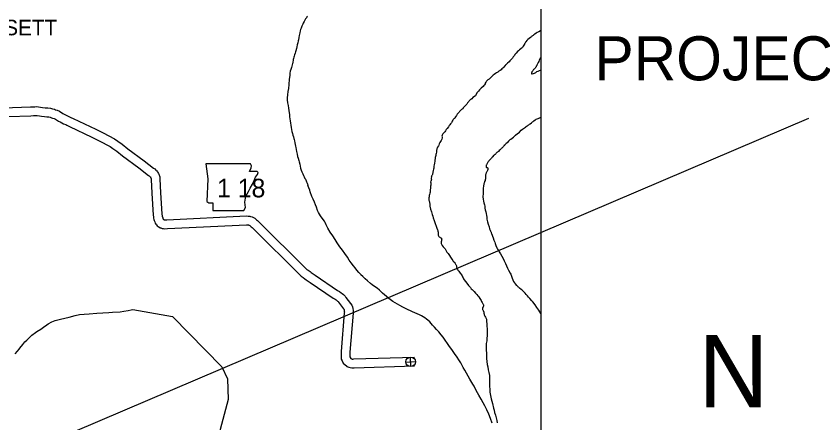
# Model space of a CAD drawing. Extents: x -117616 to 64730, y 54117 to 789866.
# Drawn here: x 62107.1 to 62382.1, y 55866.6 to 56005.1 of the extents above; entities that cross this region are included whole.
import ezdxf

# ---------------------------------------------------------------- set-up
doc = ezdxf.new("R2010")
doc.units = 0
for name, color, linetype in [('10', 7, 'Continuous'), ('21', 7, 'Continuous'), ('26', 7, 'Continuous'), ('3', 7, 'Continuous'), ('6', 7, 'Continuous'), ('9', 7, 'Continuous'), ('Default', 7, 'Continuous'), ('R_Draft', 7, 'Continuous'), ('R_No Plot', 7, 'Continuous')]:
    doc.layers.add(name, color=color, linetype=linetype)

msp = doc.modelspace()

# ---------------------------------------------------------------- linework, layer by layer
at = {"layer": '10'}
for points in [[(62096.7, 55973.7), (62111.98, 55974.22), (62112.83, 55974.27), (62113.46, 55974.3), (62114, 55974.31), (62114.69, 55974.23), (62115.44, 55974.13), (62116.12, 55974.04), (62117.04, 55973.91), (62117.85, 55973.88), (62118.77, 55973.75), (62119.49, 55973.59), (62120.15, 55973.4), (62120.48, 55973.27), (62121.13, 55973.06), (62121.88, 55972.72), (62123.04, 55972.01), (62123.52, 55971.76), (62124.1, 55971.46), (62124.59, 55971.19), (62125.26, 55970.9), (62125.72, 55970.67), (62126.59, 55970.27), (62134.27, 55966.66), (62136.8, 55965.35), (62140.66, 55963.31), (62141.74, 55962.58), (62143.22, 55961.54), (62145.18, 55960), (62150.71, 55955.82), (62153.97, 55953.35), (62154.4, 55953.09), (62154.74, 55952.72), (62154.84, 55952.62), (62155.05, 55952.42), (62155.26, 55952.17), (62155.46, 55951.91), (62155.67, 55951.5), (62155.76, 55951.28), (62155.88, 55951.02), (62155.97, 55950.71), (62156.05, 55950.39), (62156.14, 55949.76), (62156.35, 55945.01)], [(62096.82, 55970.7), (62112.12, 55971.22), (62112.99, 55971.28), (62113.55, 55971.3), (62113.85, 55971.31), (62114.32, 55971.25), (62115.04, 55971.16), (62115.71, 55971.07), (62116.78, 55970.92), (62117.59, 55970.89), (62118.22, 55970.8), (62118.74, 55970.68), (62119.2, 55970.55), (62119.48, 55970.44), (62120.05, 55970.26), (62120.47, 55970.07), (62121.57, 55969.39), (62122.14, 55969.1), (62122.69, 55968.81), (62123.27, 55968.49), (62123.99, 55968.18), (62124.43, 55967.96), (62125.33, 55967.55), (62132.94, 55963.97), (62135.41, 55962.69), (62139.11, 55960.74), (62140.03, 55960.11), (62141.43, 55959.13), (62143.34, 55957.62), (62148.9, 55953.43), (62152.28, 55950.87), (62152.47, 55950.75), (62152.57, 55950.64), (62152.76, 55950.45), (62152.86, 55950.36), (62152.91, 55950.3), (62152.91, 55950.29), (62152.95, 55950.23), (62153.03, 55950.03), (62153.06, 55949.97), (62153.07, 55949.93), (62153.1, 55949.81), (62153.14, 55949.5), (62153.35, 55944.87)], [(62153.35, 55944.84), (62153.83, 55937.41), (62153.89, 55936.77), (62153.94, 55936.36), (62154.05, 55935.87), (62154.19, 55935.56), (62154.27, 55935.36), (62154.31, 55935.26), (62154.36, 55935.07), (62154.52, 55934.67), (62154.78, 55934.3), (62154.92, 55934.09), (62155.23, 55933.77), (62155.49, 55933.53), (62155.74, 55933.34), (62156.18, 55933.1), (62156.4, 55933.02), (62156.7, 55932.9), (62156.84, 55932.87), (62156.96, 55932.84), (62157.18, 55932.78), (62157.61, 55932.71), (62158.68, 55932.8), (62185.61, 55934.08), (62185.99, 55934.05), (62186.22, 55934.04), (62186.39, 55934.02), (62186.45, 55934.01), (62186.56, 55933.99), (62186.58, 55933.97), (62186.74, 55933.84), (62187.2, 55933.41), (62187.53, 55933.2), (62204.28, 55916.55), (62204.98, 55916.1), (62205.49, 55915.73), (62205.95, 55915.38), (62206.67, 55914.88), (62207.35, 55914.41), (62215.13, 55909.12), (62215.82, 55908.76), (62216.16, 55908.53), (62216.36, 55908.37), (62216.71, 55908.09), (62216.88, 55907.93), (62217, 55907.71), (62218.74, 55905.41), (62218.91, 55905.19), (62218.94, 55905.09), (62218.98, 55904.71), (62218.99, 55904.3), (62218.98, 55904.14), (62217.89, 55890.88), (62217.87, 55890.22), (62217.86, 55889.73), (62217.87, 55889.3), (62217.91, 55888.85), (62217.96, 55888.32), (62218.21, 55887.74), (62218.61, 55887), (62219.79, 55885.93), (62219.89, 55885.88), (62220.16, 55885.73), (62220.5, 55885.61), (62220.94, 55885.45), (62221.49, 55885.36), (62222.03, 55885.37), (62222.38, 55885.39), (62242.94, 55886.02)], [(62156.35, 55945.03), (62156.82, 55937.65), (62156.88, 55937.09), (62156.9, 55936.85), (62156.9, 55936.84), (62156.95, 55936.76), (62157.06, 55936.48), (62157.16, 55936.22), (62157.2, 55936.07), (62157.26, 55935.98), (62157.26, 55935.98), (62157.32, 55935.93), (62157.4, 55935.85), (62157.41, 55935.85), (62157.45, 55935.83), (62157.59, 55935.78), (62157.72, 55935.75), (62157.76, 55935.73), (62158.48, 55935.79), (62185.68, 55937.09), (62186.17, 55937.04), (62186.4, 55937.04), (62186.76, 55937), (62187.04, 55936.96), (62187.58, 55936.83), (62188.03, 55936.62), (62188.44, 55936.33), (62188.74, 55936.07), (62189.05, 55935.79), (62189.43, 55935.53), (62206.15, 55918.91), (62206.66, 55918.59), (62207.29, 55918.14), (62207.72, 55917.81), (62208.39, 55917.35), (62209.05, 55916.88), (62216.68, 55911.7), (62217.35, 55911.34), (62217.96, 55910.94), (62218.26, 55910.69), (62218.69, 55910.35), (62219.28, 55909.78), (62219.52, 55909.36), (62221.11, 55907.25), (62221.58, 55906.66), (62221.77, 55906.18), (62221.9, 55905.57), (62221.98, 55904.91), (62221.99, 55904.3), (62221.98, 55903.98), (62220.89, 55890.71), (62220.87, 55890.13), (62220.86, 55889.72), (62220.87, 55889.47), (62220.9, 55889.13), (62220.9, 55889.1), (62221.19, 55888.59), (62221.2, 55888.59), (62221.41, 55888.47), (62221.51, 55888.44), (62221.7, 55888.37), (62221.7, 55888.36), (62221.93, 55888.37), (62222.26, 55888.38), (62242.85, 55889.02)]]:
    msp.add_lwpolyline(points, dxfattribs=at)
at = {"layer": '21'}
msp.add_lwpolyline([(62171.73, 55954.8), (62172.5, 55949.72), (62172.16, 55942.03), (62172.84, 55941.6), (62174.11, 55941.6), (62174.11, 55938.9), (62184.77, 55938.9), (62185.28, 55940), (62185.11, 55941.78), (62185.36, 55943.81), (62186.29, 55945.42), (62186.88, 55946.6), (62187.73, 55947.87), (62188.23, 55949.22), (62188.66, 55950.32), (62189.42, 55951.25), (62189.58, 55951.85), (62189.25, 55952.27), (62186.62, 55952.27), (62187.22, 55953.45), (62187.3, 55954.21), (62186.95, 55954.8)], close=True, dxfattribs=at)
at = {"layer": '26'}
for p, q in [((62239.98, 55887.32), (62243.22, 55887.52)), ((62241.7, 55885.8), (62241.5, 55889.04))]:
    msp.add_line(p, q, dxfattribs=at)
msp.add_circle((62241.6, 55887.42), 1.62, dxfattribs=at)
at = {"layer": '3'}
for points in [[(62206.39, 56005.17), (62206.24, 56004.88), (62206.05, 56004.6), (62205.8, 56004.24), (62205.66, 56004.02), (62205.24, 56003.29), (62204.99, 56002.69), (62204.85, 56002.41), (62204.5, 56001.74), (62204.22, 56001.06), (62204.05, 56000.57), (62203.94, 56000.12), (62203.81, 55999.42), (62203.62, 55998.51), (62203.53, 55997.82), (62203.39, 55997.11), (62203.29, 55996.71), (62203.12, 55996), (62202.95, 55995.39), (62202.78, 55994.65), (62202.65, 55994.11), (62202.45, 55993.32), (62202.33, 55992.94), (62202.21, 55992.52), (62202.04, 55991.96), (62201.9, 55991.49), (62201.78, 55991.11), (62201.65, 55990.72), (62201.57, 55990.38), (62201.5, 55989.99), (62201.44, 55989.6), (62201.38, 55989.24), (62201.33, 55988.97), (62201.22, 55988.56), (62201.08, 55988.09), (62200.93, 55987.65), (62200.72, 55986.94), (62200.57, 55986.35), (62200.45, 55985.75), (62200.44, 55984.9), (62200.2, 55983.64), (62200.12, 55981.9), (62199.93, 55980.54), (62199.76, 55979.45), (62199.56, 55978.3), (62199.48, 55977.37), (62199.49, 55976.64), (62199.6, 55975.63), (62199.8, 55974.66), (62199.98, 55973.74), (62200.09, 55973.05), (62200.19, 55972.22)], [(62200.19, 55972.22), (62200.25, 55971.64), (62200.34, 55970.9), (62200.55, 55969.45), (62200.66, 55968.72), (62200.78, 55967.97), (62200.89, 55967.17), (62200.98, 55966.53), (62201.1, 55965.85), (62201.27, 55965.15), (62201.45, 55964.55), (62201.62, 55963.99), (62201.77, 55963.47), (62201.87, 55963.14), (62201.97, 55962.7), (62202.12, 55962.03), (62202.24, 55961.47), (62202.35, 55960.9), (62202.44, 55960.36), (62202.56, 55959.76), (62202.72, 55959.01), (62202.91, 55958.09), (62203.07, 55957.37), (62203.21, 55956.82), (62203.45, 55956.03), (62203.58, 55955.55), (62203.76, 55954.73), (62203.91, 55954.06), (62204.09, 55953.32), (62204.28, 55952.71), (62204.51, 55952.1), (62204.82, 55951.45), (62205.09, 55950.83), (62205.31, 55950.38), (62205.56, 55949.87), (62205.7, 55949.59), (62205.93, 55949.09), (62206.11, 55948.67), (62206.27, 55948.26), (62206.4, 55947.93), (62206.51, 55947.67), (62206.58, 55947.5)], [(62265.68, 55874.74), (62264.87, 55876.05), (62263.97, 55877.69), (62263.24, 55879.13), (62262.8, 55879.85), (62261.81, 55881.46), (62261.18, 55882.59), (62260.63, 55883.59), (62260.04, 55884.56), (62259.5, 55885.46), (62259.13, 55886.18), (62258.73, 55887.03), (62258.07, 55888.06), (62257.42, 55889.02), (62256.53, 55890.25), (62255.61, 55891.6), (62254.89, 55892.65), (62254.1, 55893.71), (62253.33, 55894.83), (62252.65, 55895.83), (62252.05, 55896.62), (62251.18, 55897.62), (62250.42, 55898.48), (62249.68, 55899.24), (62249.02, 55899.95), (62248.56, 55900.52), (62248.18, 55901), (62247.5, 55901.58), (62247.02, 55902), (62246.48, 55902.4), (62245.86, 55902.76), (62245.33, 55903.06), (62244.56, 55903.41), (62243.76, 55903.8), (62242.18, 55904.49), (62241.52, 55904.8), (62240.78, 55905.16), (62239.85, 55905.59), (62238.9, 55906.08), (62237.86, 55906.65), (62236.35, 55907.52), (62235.56, 55908), (62234.14, 55909.03), (62233.34, 55909.61), (62231.98, 55910.85), (62230.99, 55911.83), (62230.15, 55912.47), (62229.26, 55913.06), (62228.49, 55913.67), (62227.94, 55914.14), (62226.83, 55915.04), (62226.13, 55915.66), (62225.25, 55916.42), (62224.6, 55917.09), (62224.48, 55917.25), (62223.97, 55917.79), (62223.21, 55918.65), (62222.67, 55919.37), (62222.11, 55920.06), (62221.31, 55921.12), (62220.66, 55922.08), (62220.02, 55923.01), (62219.14, 55924.26), (62218.35, 55925.4), (62217.49, 55926.62), (62216.57, 55927.97), (62215.84, 55929.06), (62215.02, 55930.27), (62214.2, 55931.54), (62213.41, 55932.95), (62212.83, 55934.1), (62212.45, 55934.82), (62212.2, 55935.28), (62211.42, 55936.37), (62210.87, 55937.17), (62210.22, 55938.28), (62209.87, 55939), (62209.44, 55940.05), (62209.1, 55940.89), (62208.78, 55941.8), (62208.41, 55942.8), (62207.91, 55943.75), (62207.36, 55945.36), (62207.22, 55945.89), (62206.58, 55947.5)], [(62106.82, 55890.17), (62107.52, 55891.06), (62108.16, 55891.74), (62108.39, 55892.1), (62109.39, 55893.34), (62110.12, 55894.17), (62110.71, 55894.81), (62111.43, 55895.49), (62112.49, 55896.52), (62113.7, 55897.36), (62114.2, 55897.72), (62115.5, 55898.55), (62116.48, 55899.23), (62117.55, 55900), (62118.07, 55900.38), (62119.23, 55901.09), (62120.36, 55901.46), (62122.24, 55901.99), (62125.15, 55902.59), (62127.21, 55903.14), (62128.68, 55903.48), (62130.3, 55903.63), (62132.05, 55903.77), (62134.62, 55903.98), (62136.62, 55904.06), (62138.71, 55904.21), (62140, 55904.3), (62142.58, 55904.47), (62143.77, 55904.62), (62145.26, 55904.91), (62146.33, 55905.16), (62146.93, 55905.27), (62160.39, 55902.89), (62177.19, 55885.76), (62179.12, 55881.62), (62179.37, 55874.54), (62174.3, 55855.4)], [(62269.37, 55866.58), (62268.78, 55868.11), (62268.19, 55869.59), (62267.54, 55871.11), (62266.89, 55872.42), (62266.37, 55873.45), (62265.68, 55874.74)]]:
    msp.add_lwpolyline(points, dxfattribs=at)
at = {"layer": '9'}
for points in [[(62285.97, 56000.15), (62285.83, 56000.09), (62285.25, 55999.81), (62284.71, 55999.52), (62284.37, 55999.29), (62283.98, 55999.02), (62283.61, 55998.75), (62283.33, 55998.55), (62282.95, 55998.28), (62282.75, 55998.12), (62282.44, 55997.89), (62282, 55997.53), (62281.57, 55997.14), (62281.18, 55996.82), (62280.9, 55996.43), (62280.77, 55996.25), (62280.5, 55995.81), (62280.19, 55995.28), (62279.99, 55994.95), (62279.68, 55994.49), (62279.21, 55994.01), (62278.75, 55993.64), (62278.35, 55993.31), (62278.05, 55993.04), (62277.6, 55992.55), (62277.16, 55992.05), (62276.96, 55991.78), (62276.58, 55991.24), (62276.28, 55990.86), (62275.79, 55990.31), (62275.45, 55989.92), (62275.21, 55989.58), (62274.64, 55989.12), (62274.38, 55988.91), (62274.26, 55988.81), (62274.11, 55988.67), (62273.99, 55988.54), (62273.86, 55988.4), (62273.76, 55988.26), (62273.62, 55988.12)], [(62285.97, 55991.11), (62285.87, 55990.98), (62285.77, 55990.81), (62285.47, 55990.34), (62285.41, 55990.13), (62285.26, 55989.69), (62285.08, 55989.35), (62284.94, 55989), (62284.87, 55988.86), (62284.71, 55988.62), (62284.61, 55988.45), (62284.56, 55988.33), (62284.48, 55988.17), (62284.41, 55988.06), (62284.37, 55987.96), (62284.33, 55987.84), (62284.21, 55987.62), (62284.04, 55987.44), (62283.83, 55987.23), (62283.66, 55987.1), (62283.5, 55986.94), (62283.38, 55986.79), (62283.35, 55986.74), (62283.19, 55986.53), (62283.11, 55986.44), (62283.02, 55986.3), (62282.96, 55986.14), (62282.9, 55986.02), (62282.88, 55985.96), (62282.86, 55985.92), (62282.82, 55985.81), (62282.81, 55985.8), (62282.8, 55985.74), (62282.8, 55985.7)], [(62273.62, 55988.12), (62273.22, 55987.63), (62272.99, 55987.43), (62272.72, 55987.18), (62272.41, 55986.9), (62272.07, 55986.64), (62271.68, 55986.34), (62271.37, 55986.07), (62270.91, 55985.79), (62270.55, 55985.55), (62270.11, 55985.3), (62269.77, 55985.02), (62269.33, 55984.66), (62269.02, 55984.38), (62268.66, 55984.01), (62268.32, 55983.71), (62267.85, 55983.4), (62267.58, 55983.14), (62267.47, 55982.97), (62267.35, 55982.81), (62267.22, 55982.64), (62267.04, 55982.34), (62266.94, 55982.1), (62266.76, 55981.73), (62266.53, 55981.47), (62266.33, 55981.23), (62265.59, 55980.55), (62265.1, 55980.03), (62264.68, 55979.58), (62264.12, 55979.03), (62263.67, 55978.05), (62262.8, 55977.41), (62262.4, 55976.94), (62262.14, 55976.73), (62261.93, 55976.59), (62261.69, 55976.4), (62261.52, 55976.25), (62261.38, 55976.09), (62261.19, 55975.86), (62261, 55975.56), (62260.74, 55975.15), (62260.34, 55974.74), (62259.99, 55974.38), (62259.54, 55973.86), (62259.33, 55973.62), (62258.97, 55973.31), (62258.72, 55973.07), (62258.58, 55972.95), (62258.29, 55972.63), (62258.11, 55972.4), (62257.86, 55972.17), (62257.71, 55971.98), (62257.49, 55971.71), (62257.27, 55971.32), (62256.9, 55970.8), (62256.69, 55970.53), (62256.49, 55970.3), (62256.29, 55970.12), (62256.11, 55969.94), (62255.95, 55969.75), (62255.75, 55969.35), (62255.62, 55969.04), (62255.48, 55968.81), (62255.2, 55968.48), (62254.93, 55968.16), (62254.7, 55967.87), (62254.45, 55967.48), (62254.04, 55966.92), (62253.73, 55966.53), (62253.46, 55966.11), (62253.22, 55965.69), (62252.94, 55965.4), (62252.73, 55965.21), (62252.59, 55965.08), (62252.44, 55964.85), (62252.33, 55964.55), (62252.28, 55964.28), (62252.31, 55964), (62252.34, 55963.79), (62252.38, 55963.67), (62252.28, 55963.24), (62251.96, 55962.83), (62251.74, 55962.5), (62251.55, 55962.05), (62251.35, 55961.62), (62251.2, 55961.25), (62251.08, 55961.01), (62250.77, 55960.53), (62250.62, 55960.19), (62250.52, 55959.97), (62250.44, 55959.43), (62250.43, 55959.23), (62250.37, 55958.84), (62250.3, 55958.4), (62250.23, 55957.99), (62250.17, 55957.64), (62250.09, 55957.36), (62249.99, 55957.02), (62249.93, 55956.61), (62249.87, 55956.12), (62249.82, 55955.7)], [(62282.8, 55985.7), (62282.79, 55985.65), (62282.79, 55985.64), (62282.84, 55985.54), (62282.91, 55985.53), (62283.06, 55985.53), (62283.43, 55985.57), (62283.77, 55985.71), (62284.08, 55985.85), (62284.26, 55985.99), (62284.63, 55986.29), (62285.02, 55986.44), (62285.28, 55986.53), (62285.55, 55986.61), (62285.89, 55986.7), (62285.97, 55986.73)], [(62274.96, 55962.6), (62275.49, 55963.13), (62275.72, 55963.29), (62276.24, 55963.63), (62276.64, 55963.92), (62277.39, 55964.61), (62278.04, 55965.2), (62278.21, 55965.32), (62278.65, 55965.67), (62279.3, 55966.3), (62279.71, 55966.69), (62280.1, 55966.88), (62280.42, 55967.13), (62280.72, 55967.35), (62281.01, 55967.54), (62281.29, 55967.73), (62281.57, 55967.91), (62281.7, 55968.01), (62281.87, 55968.14), (62282.14, 55968.34), (62282.39, 55968.5), (62282.76, 55968.78), (62283.14, 55969.09), (62283.34, 55969.24), (62283.62, 55969.47), (62284.03, 55969.8), (62284.28, 55969.93), (62284.42, 55970.01), (62285.01, 55970.32), (62285.47, 55970.48), (62285.47, 55970.49), (62285.66, 55970.55), (62285.81, 55970.61), (62285.97, 55970.67)], [(62274.96, 55962.6), (62274.5, 55962.03), (62274.17, 55961.8), (62273.97, 55961.57), (62273.78, 55961.36), (62273.52, 55961.12), (62273.42, 55960.98), (62273.29, 55960.84), (62273.11, 55960.65), (62272.98, 55960.5), (62272.77, 55960.3), (62272.65, 55960.18), (62272.49, 55960.01), (62272.32, 55959.84), (62272.09, 55959.61), (62271.75, 55959.33), (62271.49, 55959.09), (62271.32, 55958.94), (62271.18, 55958.82), (62271.02, 55958.67), (62270.9, 55958.57), (62270.77, 55958.43), (62270.58, 55958.26), (62270.37, 55958.07), (62270.25, 55958), (62270.02, 55957.83), (62269.87, 55957.65), (62269.66, 55957.38), (62269.53, 55957.22), (62269.44, 55957.09), (62269.3, 55956.94), (62269.16, 55956.8), (62269.03, 55956.68), (62268.83, 55956.47), (62268.7, 55956.33), (62268.56, 55956.18), (62268.41, 55956.03), (62268.26, 55955.86), (62268.12, 55955.63), (62267.93, 55955.41), (62267.77, 55955.2), (62267.64, 55954.97), (62267.52, 55954.76), (62267.43, 55954.54), (62267.37, 55954.39), (62267.33, 55954.2), (62267.32, 55954.05), (62267.32, 55953.95), (62267.34, 55953.87), (62267.34, 55953.81), (62267.35, 55953.76), (62267.35, 55953.72), (62267.38, 55953.65), (62267.39, 55953.65), (62267.44, 55953.55), (62267.56, 55953.57), (62267.6, 55953.58), (62267.65, 55953.6), (62267.77, 55953.57), (62267.84, 55953.51), (62267.91, 55953.4), (62267.91, 55953.33), (62267.96, 55953.06), (62267.92, 55952.9), (62267.83, 55952.61), (62267.69, 55952.34), (62267.58, 55952.14), (62267.49, 55951.95), (62267.39, 55951.75), (62267.31, 55951.61), (62267.25, 55951.45), (62267.19, 55951.27), (62267.15, 55951.1), (62267.14, 55950.98), (62267.13, 55950.84), (62267.13, 55950.73), (62267.15, 55950.62), (62267.15, 55950.57)], [(62249.82, 55955.7), (62249.72, 55955.07), (62249.6, 55954.48), (62249.55, 55954.1), (62249.51, 55953.83), (62249.45, 55953.34), (62249.39, 55953.03), (62249.31, 55952.6), (62249.23, 55952.3), (62249.18, 55952.06), (62249.15, 55951.78), (62249.1, 55951.62), (62249.06, 55951.44), (62248.99, 55951.24), (62248.88, 55951.02), (62248.81, 55950.82), (62248.7, 55950.62), (62248.66, 55950.44), (62248.64, 55950.25), (62248.65, 55950.08), (62248.64, 55949.89), (62248.64, 55949.69), (62248.69, 55949.46)], [(62267.15, 55950.57), (62267.1, 55949.71), (62266.99, 55949.41), (62266.95, 55949.2), (62266.76, 55948.77), (62266.66, 55948.3), (62266.54, 55947.99), (62266.4, 55947.21), (62266.35, 55946.59), (62266.29, 55945.02), (62266.28, 55944.71), (62266.18, 55943.62), (62266.27, 55942.77), (62266.44, 55942.1), (62266.59, 55941.58), (62266.78, 55940.93), (62266.87, 55940.38), (62266.86, 55940.1), (62266.89, 55939.76), (62266.96, 55939.2), (62267.17, 55938.48), (62267.29, 55937.93), (62267.4, 55937.25), (62267.54, 55936.63), (62267.61, 55936), (62267.77, 55935.09), (62268.02, 55934.35), (62268.36, 55933.43), (62268.5, 55932.73), (62268.66, 55932.26), (62268.79, 55931.95), (62268.88, 55931.8), (62269, 55931.55), (62269.09, 55931.36), (62269.2, 55931.07), (62269.69, 55929.6), (62269.99, 55928.9), (62270.25, 55928.14), (62270.41, 55927.67), (62270.67, 55926.99), (62271.02, 55926.25), (62271.21, 55925.8), (62271.52, 55925.32), (62271.82, 55924.84), (62272.21, 55924.15), (62272.71, 55923.43), (62273.1, 55922.63), (62273.49, 55921.82), (62273.91, 55920.87), (62274.22, 55920.06), (62274.58, 55919.36), (62274.95, 55918.65), (62275.51, 55917.61), (62275.71, 55917.24), (62275.83, 55916.88), (62276.09, 55916.3), (62276.22, 55915.88), (62276.43, 55915.29), (62276.71, 55914.73), (62277, 55914.36), (62277.3, 55913.96)], [(62248.69, 55949.46), (62248.45, 55948.87), (62248.39, 55948.66), (62248.42, 55948.37), (62248.43, 55948.12), (62248.5, 55947.63), (62248.41, 55947.21), (62248.32, 55946.64), (62248.22, 55945.88), (62248.21, 55945.16), (62248.17, 55944.85), (62248.04, 55944.45), (62247.95, 55944.04), (62247.88, 55943.65), (62247.78, 55943.24), (62247.74, 55942.91), (62247.82, 55942.44), (62247.88, 55942.25), (62248.11, 55941.14), (62248.17, 55940.38), (62248.4, 55939.37), (62248.67, 55938.53), (62248.96, 55937.61), (62249.13, 55937.03), (62249.26, 55936.41), (62249.6, 55935.49), (62249.95, 55934.48), (62250.25, 55933.58), (62250.49, 55932.93), (62250.72, 55932.42), (62250.83, 55932.15), (62250.9, 55931.88), (62250.94, 55931.58), (62250.94, 55931.23), (62250.95, 55930.97), (62250.98, 55930.57), (62251.05, 55930.3), (62251.2, 55930.05), (62251.36, 55929.93), (62251.51, 55929.85), (62251.66, 55929.76), (62251.83, 55929.67), (62252.06, 55929.48), (62252.12, 55929.38), (62252.15, 55929.25), (62252.18, 55929.12), (62252.15, 55928.91), (62252.09, 55928.68), (62252.06, 55928.5), (62252.02, 55928.36), (62252.03, 55928.29), (62251.99, 55927.96), (62252.02, 55927.7), (62252.11, 55927.45), (62252.36, 55927.01), (62252.7, 55926.54), (62253.31, 55925.93), (62253.43, 55925.62), (62253.93, 55924.77), (62254.37, 55924.26), (62254.83, 55923.65), (62255.23, 55923.02), (62255.59, 55922.33), (62255.92, 55921.88), (62256.14, 55921.7), (62256.6, 55921.29), (62256.63, 55921.11), (62256.87, 55920.72), (62257.01, 55920.51), (62257.08, 55920.37), (62257.18, 55920.09), (62257.21, 55919.88), (62257.24, 55919.6), (62257.29, 55919.38), (62257.35, 55919.16), (62257.51, 55918.91), (62257.7, 55918.63), (62257.99, 55918.31), (62258.22, 55917.94), (62258.45, 55917.63), (62258.68, 55917.33), (62258.93, 55916.99), (62259.14, 55916.72), (62259.31, 55916.41), (62259.47, 55916), (62259.64, 55915.66), (62259.86, 55915.32), (62260.7, 55914.21), (62261.35, 55913.46), (62261.98, 55912.74), (62262.25, 55912.32), (62262.54, 55912.01), (62262.88, 55911.69), (62263.26, 55911.31), (62263.71, 55910.82), (62264.11, 55910.37), (62264.54, 55909.88), (62264.85, 55909.51), (62265.23, 55908.99), (62265.59, 55908.33), (62265.79, 55907.94)], [(62285.97, 55903.92), (62285.24, 55904.96), (62284.63, 55905.9), (62284.02, 55906.77), (62283.19, 55907.85), (62282.85, 55908.23), (62282.18, 55908.95), (62281.81, 55909.41), (62281.4, 55909.89), (62281.03, 55910.34), (62280.68, 55910.78), (62280.37, 55911.03), (62279.91, 55911.47), (62279.59, 55911.79), (62279.31, 55912.02), (62278.71, 55912.51), (62278.49, 55912.69), (62278.4, 55912.77), (62278.26, 55912.95), (62278.12, 55913.05), (62277.93, 55913.25), (62277.87, 55913.35), (62277.81, 55913.43), (62277.3, 55913.96)], [(62265.79, 55907.94), (62265.98, 55907.63), (62266.13, 55907.4), (62266.24, 55907.22), (62266.34, 55907.05), (62266.42, 55906.87), (62266.46, 55906.75), (62266.45, 55906.57), (62266.41, 55906.41), (62266.37, 55906.27), (62266.29, 55906), (62266.14, 55905.8), (62266.08, 55905.66), (62266.08, 55905.44), (62266.12, 55905.26), (62266.23, 55905.09), (62266.34, 55904.91), (62266.49, 55904.37), (62266.54, 55904.01), (62266.63, 55903.61), (62266.71, 55903.37), (62266.92, 55902.94), (62267.08, 55902.66), (62267.26, 55902.35), (62267.4, 55901.95), (62267.49, 55901.36), (62267.52, 55900.18), (62267.58, 55899.38), (62267.63, 55898.84), (62267.66, 55897.74), (62267.66, 55896.84), (62267.64, 55896.26), (62267.62, 55895.45), (62267.58, 55895.07), (62267.52, 55894.52), (62267.37, 55893.7), (62267.32, 55892.99), (62267.34, 55892.24), (62267.35, 55891.44), (62267.4, 55890.36), (62267.45, 55889.42), (62267.48, 55888.54), (62267.6, 55887.52), (62267.73, 55886.52), (62267.87, 55885.69), (62268.05, 55884.74), (62268.27, 55883.82), (62268.43, 55882.79), (62268.45, 55881.79), (62268.47, 55880.83), (62268.43, 55879.94), (62268.46, 55879.05), (62268.55, 55878.16), (62268.64, 55877.12), (62268.81, 55875.96), (62269.07, 55874.86), (62269.26, 55874.07), (62269.49, 55873.2), (62269.84, 55871.66), (62270.01, 55870.99), (62270.22, 55870.18), (62270.48, 55869.23), (62270.72, 55868.32), (62270.93, 55867.43), (62271.12, 55866.62)]]:
    msp.add_lwpolyline(points, dxfattribs=at)
at = {"layer": 'R_Draft'}
msp.add_line((61948.13, 55787.58), (62377.34, 55970.42), dxfattribs=at)
at = {"layer": 'R_No Plot'}
msp.add_lwpolyline([(61556.57, 56155.54), (62285.97, 56155.54), (62285.97, 55371.05), (61556.57, 55371.05)], close=True, dxfattribs=at)

# ---------------------------------------------------------------- texts
at = {"layer": '21'}
msp.add_text('1 18', height=6.336, dxfattribs=at).set_placement((62175.57, 55943.42))
at = {"layer": '6'}
msp.add_text('BASSETT', height=5.28, dxfattribs=at).set_placement((62088.92, 55998.61))
at = {"layer": 'Default'}
msp.add_text('PROJECT AREA', height=15, dxfattribs=at).set_placement((62304.26, 55983.27))
at = {"layer": 'R_Draft'}
msp.add_text('N', height=24.73, dxfattribs=at).set_placement((62339.71, 55871.87))

doc.saveas('drawing.dxf')
